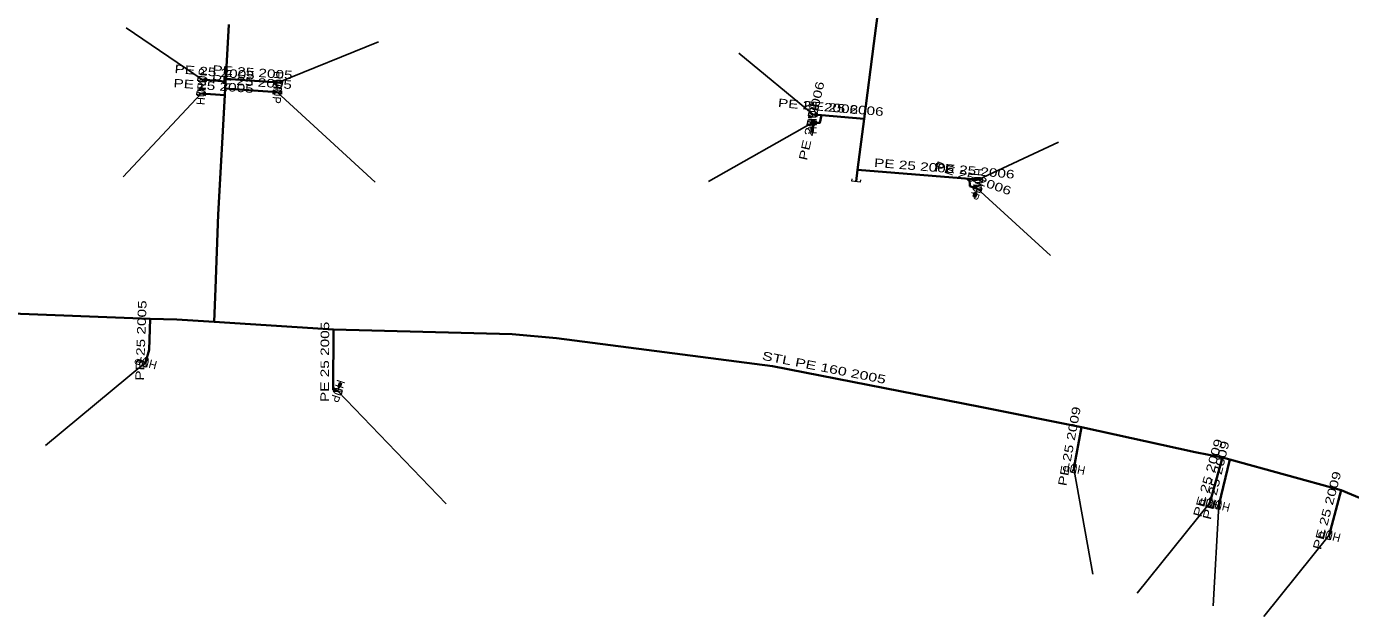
# Model space of a CAD drawing. Extents: x -737484 to -734496, y -1033882 to -1030666.
# Drawn here: x -736648.9 to -736493.3, y -1030948.8 to -1030879.4 of the extents above; entities that cross this region are included whole.
import ezdxf
from ezdxf.enums import TextEntityAlignment as Align

# ---------------------------------------------------------------- set-up
doc = ezdxf.new("R2010")
doc.units = 0
doc.header["$LTSCALE"] = 0.4
for name, color, linetype, lineweight in [('1', 7, 'Continuous', 13), ('22', 7, 'Continuous', 25), ('5', 7, 'Continuous', 35), ('7', 7, 'Continuous', 35)]:
    doc.layers.add(name, color=color, linetype=linetype, lineweight=lineweight)
doc.layers.add('2', color=7, linetype='Continuous')

msp = doc.modelspace()

# ---------------------------------------------------------------- linework, layer by layer
at = {"layer": '1'}
for p, q in [((-736556.55, -1030890.77), (-736556.541, -1030891.269)), ((-736556.614, -1030891.346), (-736556.608, -1030891.696)), ((-736537.16, -1030898.49), (-736537.322, -1030898.962)), ((-736537.418, -1030899.009), (-736537.532, -1030899.34)), ((-736635.395, -1030918.688), (-736635.734, -1030918.598)), ((-736634.86, -1030918.91), (-736635.342, -1030918.78)), ((-736612.29, -1030922.28), (-736612.135, -1030921.804)), ((-736612.04, -1030921.756), (-736611.932, -1030921.423))]:
    msp.add_line(p, q, dxfattribs=at)
for points in [[(-736628.715, -1030885.835), (-736628.68, -1030885.437), (-736627.719, -1030885.922), (-736627.684, -1030885.524)], [(-736618.787, -1030885.875), (-736618.815, -1030886.274), (-736619.784, -1030885.805), (-736619.812, -1030886.204)], [(-736628.842, -1030887.484), (-736628.814, -1030887.085), (-736627.845, -1030887.554), (-736627.817, -1030887.155)], [(-736618.887, -1030887.005), (-736618.915, -1030887.404), (-736619.884, -1030886.935), (-736619.912, -1030887.334)], [(-736556.965, -1030889.925), (-736556.93, -1030889.527), (-736555.969, -1030890.012), (-736555.934, -1030889.614)], [(-736557.046, -1030890.978), (-736557.053, -1030890.578), (-736556.046, -1030890.961), (-736556.053, -1030890.561)], [(-736556.532, -1030891.769), (-736556.682, -1030891.772), (-736556.691, -1030891.272), (-736556.541, -1030891.269)], [(-736556.57, -1030891.732), (-736556.645, -1030891.733), (-736556.652, -1030891.308), (-736556.577, -1030891.307)], [(-736556.532, -1030891.769), (-736556.382, -1030891.767), (-736556.391, -1030891.267), (-736556.541, -1030891.269)], [(-736536.564, -1030897.284), (-736536.599, -1030897.682), (-736537.56, -1030897.197), (-736537.595, -1030897.595)], [(-736536.622, -1030898.463), (-736536.752, -1030898.841), (-736537.567, -1030898.138), (-736537.697, -1030898.516)], [(-736537.485, -1030899.435), (-736537.627, -1030899.386), (-736537.464, -1030898.913), (-736537.322, -1030898.962)], [(-736537.508, -1030899.387), (-736537.579, -1030899.363), (-736537.44, -1030898.961), (-736537.369, -1030898.985)], [(-736537.485, -1030899.435), (-736537.343, -1030899.484), (-736537.18, -1030899.011), (-736537.322, -1030898.962)], [(-736635.825, -1030918.651), (-736635.864, -1030918.796), (-736635.381, -1030918.925), (-736635.342, -1030918.78)], [(-736635.825, -1030918.651), (-736635.787, -1030918.506), (-736635.304, -1030918.635), (-736635.342, -1030918.78)], [(-736635.779, -1030918.625), (-736635.76, -1030918.552), (-736635.349, -1030918.662), (-736635.369, -1030918.735)], [(-736634.796, -1030919.444), (-736635.182, -1030919.341), (-736634.537, -1030918.478), (-736634.923, -1030918.375)], [(-736611.752, -1030922.244), (-736611.876, -1030922.624), (-736612.703, -1030921.935), (-736612.827, -1030922.315)], [(-736611.98, -1030921.328), (-736612.123, -1030921.282), (-736612.278, -1030921.758), (-736612.135, -1030921.804)], [(-736611.98, -1030921.328), (-736611.838, -1030921.375), (-736611.992, -1030921.85), (-736612.135, -1030921.804)], [(-736611.957, -1030921.376), (-736611.886, -1030921.399), (-736612.017, -1030921.803), (-736612.088, -1030921.78)], [(-736525.709, -1030931.908), (-736526.101, -1030931.832), (-736525.518, -1030930.927), (-736525.91, -1030930.851)], [(-736509.785, -1030935.925), (-736510.17, -1030935.815), (-736509.509, -1030934.964), (-736509.894, -1030934.854)], [(-736508.716, -1030936.193), (-736509.105, -1030936.096), (-736508.474, -1030935.223), (-736508.863, -1030935.126)], [(-736495.736, -1030939.734), (-736496.122, -1030939.631), (-736495.477, -1030938.768), (-736495.863, -1030938.665)]]:
    msp.add_lwpolyline(points, close=True, dxfattribs=at)
msp.add_lwpolyline([(-736550.873, -1030897.472), (-736550.903, -1030897.72), (-736551.896, -1030897.599), (-736551.865, -1030897.35)], dxfattribs=at)
at = {"layer": '22'}
for p, q in [((-736628.2, -1030885.68), (-736637.143, -1030879.584)), ((-736619.3, -1030886.04), (-736607.512, -1030881.23)), ((-736556.45, -1030889.77), (-736565.16, -1030882.577)), ((-736628.33, -1030887.32), (-736637.49, -1030897.119)), ((-736619.4, -1030887.17), (-736607.91, -1030897.735)), ((-736556.55, -1030890.77), (-736568.738, -1030897.653)), ((-736537.08, -1030897.44), (-736527.605, -1030893.044)), ((-736537.16, -1030898.49), (-736528.554, -1030906.335)), ((-736634.86, -1030918.91), (-736646.626, -1030928.66)), ((-736612.29, -1030922.28), (-736599.55, -1030935.52)), ((-736525.81, -1030931.38), (-736523.593, -1030943.791)), ((-736509.84, -1030935.39), (-736518.384, -1030946.023)), ((-736508.79, -1030935.66), (-736509.454, -1030947.512)), ((-736495.8, -1030939.2), (-736503.501, -1030948.752))]:
    msp.add_line(p, q, dxfattribs=at)
at = {"layer": '5'}
for points in [[(-736537.3, -1030790.46), (-736537.75, -1030793.87), (-736539.55, -1030807.44), (-736540.39, -1030813.73), (-736542.63, -1030830.63), (-736543.6, -1030837.99), (-736544.44, -1030844.31), (-736546.38, -1030858.92), (-736547.08, -1030864.16), (-736548.22, -1030873.02), (-736549.31, -1030881.45), (-736550.44, -1030890.28), (-736551.22, -1030896.27), (-736551.4, -1030897.66)], [(-736626.82, -1030914.15), (-736626.66, -1030910.21), (-736626.32, -1030901.54), (-736625.94, -1030894.53), (-736625.56, -1030887.52), (-736625.51, -1030886.71), (-736625.47, -1030885.91), (-736625.45, -1030885.6), (-736625.1, -1030879.21)], [(-736756.09, -1030892.38), (-736744.26, -1030896.83), (-736742.79, -1030897.39), (-736729.03, -1030902.57), (-736726.69, -1030903.45), (-736723.02, -1030904.82), (-736716.57, -1030907.38), (-736715.58, -1030907.77), (-736708.37, -1030910.63), (-736705.78, -1030911.14), (-736692.11, -1030911.64), (-736690.54, -1030911.7), (-736675.97, -1030912.23), (-736673.68, -1030912.32), (-736669.7, -1030912.47), (-736656.1, -1030912.97), (-736651.59, -1030913.13), (-736634.32, -1030913.77), (-736631.2, -1030913.88), (-736626.82, -1030914.15)], [(-736626.82, -1030914.15), (-736612.8, -1030915.02), (-736591.79, -1030915.58), (-736586.6, -1030916.06), (-736561.2, -1030919.34), (-736536.83, -1030924.14), (-736524.9, -1030926.49), (-736511.55, -1030929.45), (-736508.34, -1030930.09), (-736507.5, -1030930.29), (-736494.4, -1030933.9), (-736490.29, -1030935.64), (-736485.53, -1030937.03)]]:
    msp.add_lwpolyline(points, dxfattribs=at)
at = {"layer": '7'}
for p, q in [((-736625.47, -1030885.91), (-736628.2, -1030885.68)), ((-736625.45, -1030885.6), (-736619.3, -1030886.04)), ((-736625.56, -1030887.52), (-736628.33, -1030887.32)), ((-736625.51, -1030886.71), (-736619.4, -1030887.17)), ((-736555.45, -1030889.86), (-736556.45, -1030889.77)), ((-736550.44, -1030890.28), (-736555.45, -1030889.86)), ((-736551.22, -1030896.27), (-736538.07, -1030897.35)), ((-736538.07, -1030897.35), (-736537.08, -1030897.44)), ((-736524.9, -1030926.49), (-736525.81, -1030931.38)), ((-736508.34, -1030930.09), (-736509.84, -1030935.39)), ((-736507.5, -1030930.29), (-736508.79, -1030935.66)), ((-736494.4, -1030933.9), (-736495.8, -1030939.2))]:
    msp.add_line(p, q, dxfattribs=at)
for points in [[(-736555.45, -1030889.86), (-736555.65, -1030890.75), (-736556.55, -1030890.77)], [(-736538.07, -1030897.35), (-736538.02, -1030898.19), (-736537.16, -1030898.49)], [(-736634.32, -1030913.77), (-736634.45, -1030917.42), (-736634.86, -1030918.91)], [(-736612.8, -1030915.02), (-736612.82, -1030922.11), (-736612.29, -1030922.28)]]:
    msp.add_lwpolyline(points, dxfattribs=at)

# ---------------------------------------------------------------- texts
at = {"layer": '2', "width": 0.95}
for rotation, p in [(85, (-736627.7013, -1030885.7231)), (266, (-736619.7986, -1030886.0046)), (86, (-736627.8304, -1030887.3544)), (266, (-736619.8986, -1030887.1346)), (91, (-736556.0492, -1030890.7602)), (85, (-736555.9513, -1030889.8131)), (251, (-736537.632, -1030898.3267)), (265, (-736537.5777, -1030897.3959)), (165, (-736634.7301, -1030918.4267)), (252, (-736612.765, -1030922.125)), (169, (-736525.7141, -1030930.8889)), (164, (-736509.7017, -1030934.9092)), (166, (-736508.6685, -1030935.174)), (165, (-736495.6701, -1030938.7167))]:
    msp.add_text('HUP', height=1, rotation=rotation, dxfattribs=at).set_placement(p, align=Align.CENTER)
at = {"layer": '5', "width": 1.4}
msp.add_text('STL PE 160 2005', height=1, rotation=348.857, dxfattribs=at).set_placement((-736555.2501, -1030920.0017), align=Align.CENTER)
at = {"layer": '7', "width": 1.35}
for s, rotation, p in [('PE 25 2005', 355.184, (-736626.793, -1030885.2959)), ('PE 25 2005', 355.908, (-736622.3392, -1030885.3205)), ('PE 25 2005', 355.87, (-736626.9085, -1030886.9206)), ('PE 25 2005', 355.695, (-736622.4165, -1030886.4413)), ('PE 25 2006', 77.335, (-736556.1359, -1030890.6341)), ('PE 25 2006', 354.857, (-736555.9043, -1030889.3162)), ('PE 25 2006', 355.208, (-736552.9028, -1030889.5709)), ('PE 25 2006', 355.305, (-736544.6034, -1030896.3108)), ('PE 25 2006', 340.769, (-736537.8222, -1030897.7285)), ('PE 25 2006', 354.806, (-736537.5288, -1030896.8965)), ('PE 25 2005', 87.96, (-736634.9112, -1030916.3488)), ('PE 25 2005', 89.838, (-736613.3105, -1030918.8414)), ('PE 25 2009', 79.458, (-736525.846, -1030928.843)), ('PE 25 2009', 74.197, (-736509.5701, -1030932.6032)), ('PE 25 2009', 76.492, (-736508.6311, -1030932.8578)), ('PE 25 2009', 75.203, (-736495.5834, -1030936.4222))]:
    msp.add_text(s, height=1, rotation=rotation, dxfattribs=at).set_placement(p, align=Align.CENTER)

doc.saveas('drawing.dxf')
